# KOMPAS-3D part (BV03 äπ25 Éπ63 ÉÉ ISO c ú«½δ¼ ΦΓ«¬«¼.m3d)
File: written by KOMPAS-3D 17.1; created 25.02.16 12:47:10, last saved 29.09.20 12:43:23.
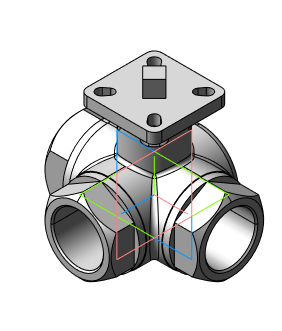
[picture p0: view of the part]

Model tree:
1. Операция без истории:3  (labels: Сталь 20  ГОСТ 1050-88)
